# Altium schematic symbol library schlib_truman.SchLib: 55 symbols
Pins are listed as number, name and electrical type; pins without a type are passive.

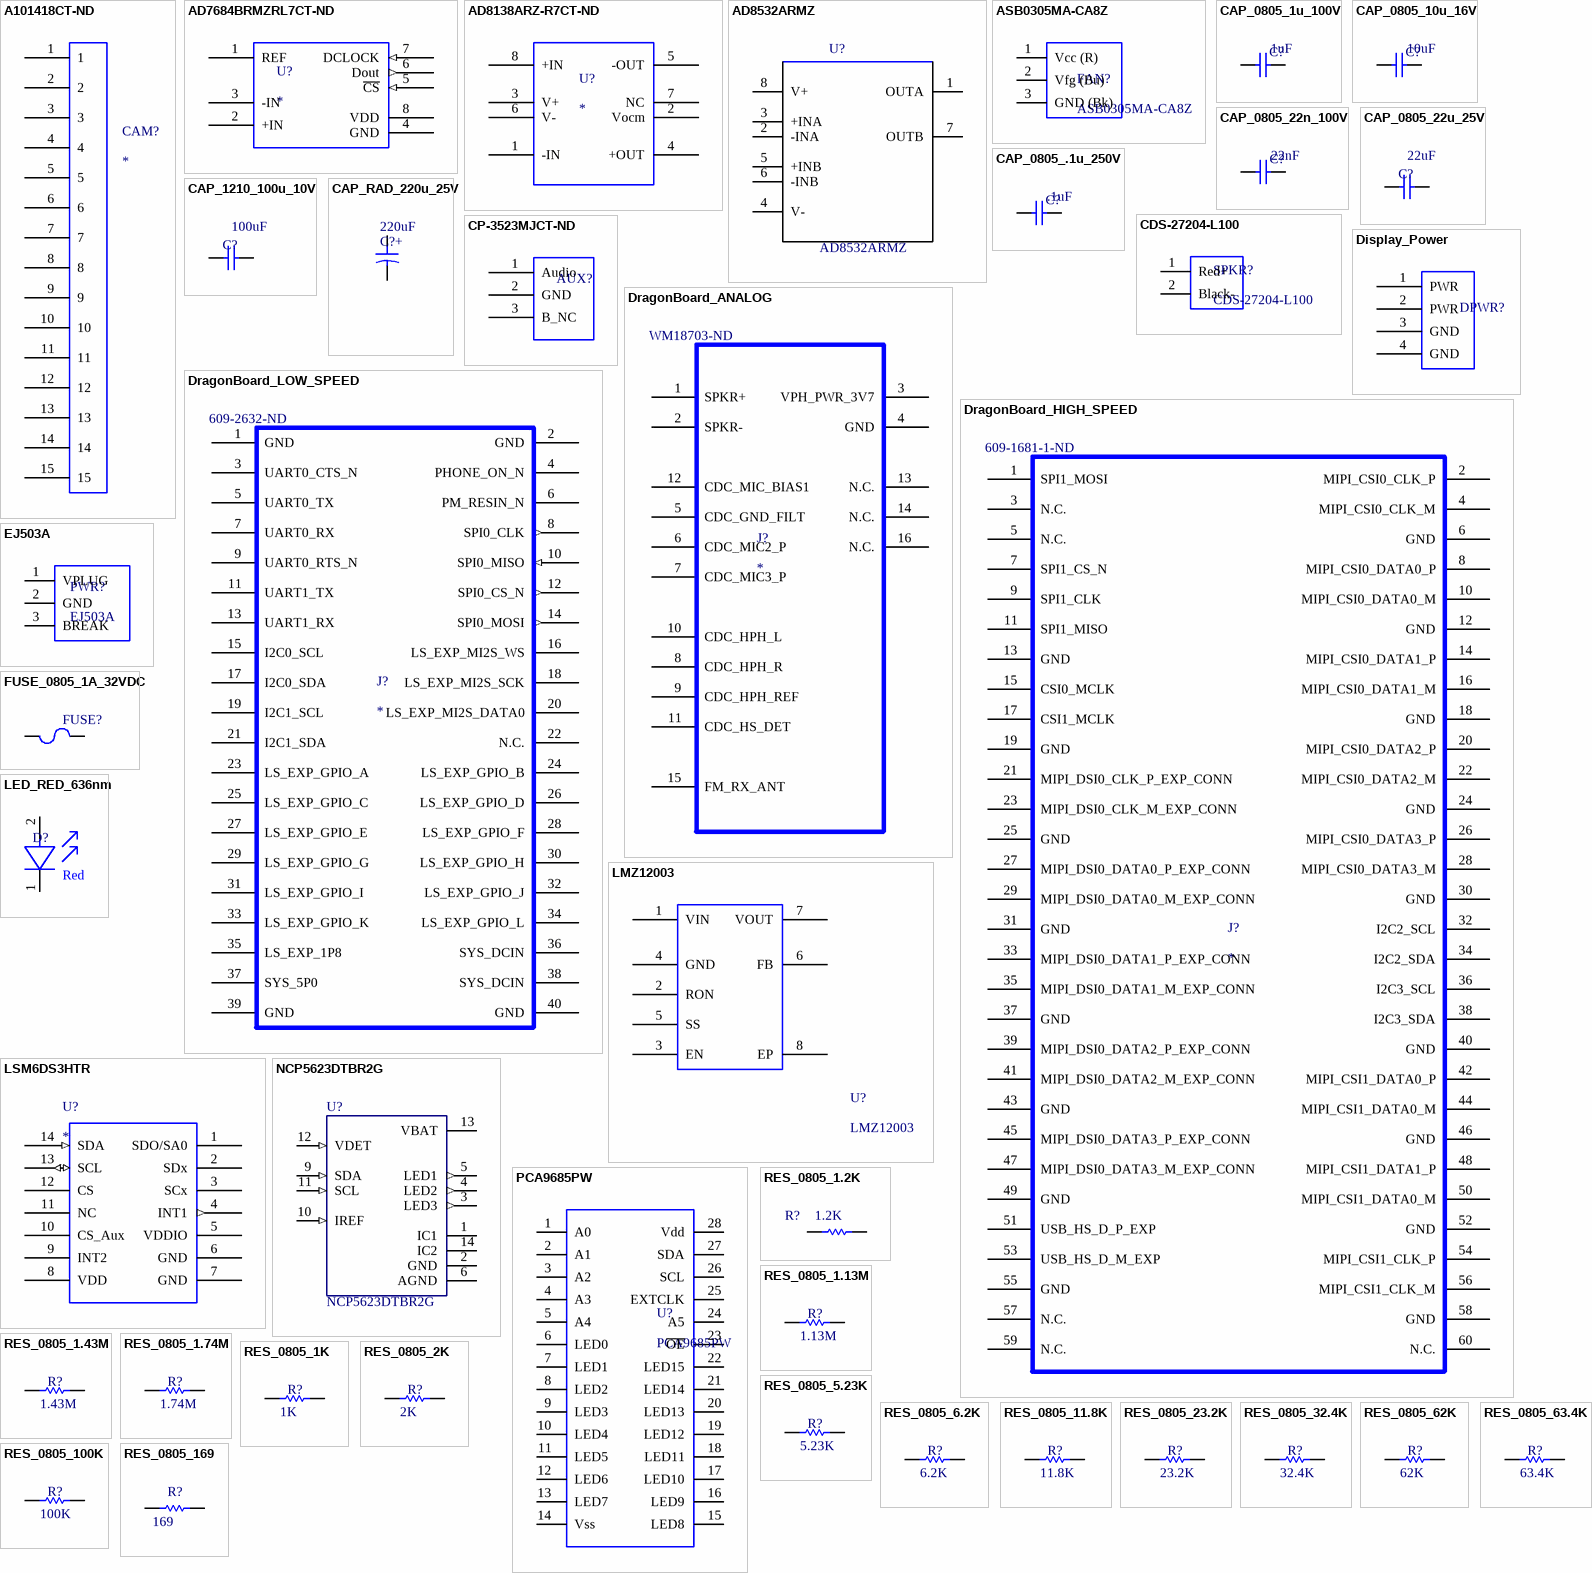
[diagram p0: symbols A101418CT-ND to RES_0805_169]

## A101418CT-ND
designator CAM?
CONN FPC VERT 15POS 1.00MM SMD; Manufacturer: TE Connectivity; Manufacturer Part Number: 1-1734248-5; Current Rating: 1A; Voltage Rating: 125V; Gender: Receptacle; Number of Positions: 15; Shielding: Unshielded; Connector Type: Connector,Receptacle,Socket; Wire/Cable Type: Flat Flex; Connector System: Flex-to-Board; Mating Alignment: Yes (With); PCB Mount Alignment: No (Without); PCB Mount Retention: With; PCB Mounting Orientation: Vertical; Pitch: 0.039inch
footprint ZIF_15pin
pins: 1, 2, 3, 4, 5, 6, 7, 8, 9, 10, 11, 12, 13, 14, 15

## AD7684BRMZRL7CT-ND
designator U?
IC ADC 16BIT 100KSPS DIFF 8MSOP; Manufacturer: Analog Devices; Manufacturer Part Number: AD7684BRMZRL7; Max Power Dissipation: 6mW; Supply Voltage: 5V; Min Supply Voltage: 2.7V; Max Supply Voltage: 5.5V; Number of Channels: 1; Interface: SPI; Power Consumption: 4mW; Resolution: 16b; Sampling Rate: 100KS/s; Signal to Noise Ratio (SNR): 91dB; Number of Bits: 16; Polarity: Bipolar; Supply Type: Single; Integral Nonlinearity (INL): 3LSB; Input Capacitance: 30pF; Full Scale Error: 15LSB; Min Input Voltage: 500mV
footprint MSOP8
pins: 1 REF, 2 +IN, 3 -IN, 4 GND, 5 ~{CS} (in), 6 Dout (out), 7 DCLOCK (in), 8 VDD

## AD8138ARZ-R7CT-ND
designator U?
SP Amp Differential ADC Driver Single ±5.5V/11V 8-Pin SOIC N T/R; Manufacturer: Analog Devices; Manufacturer Part Number: AD8138ARZ-R7; Min Supply Voltage: 2.7V; Max Supply Voltage: 11V; Min Dual Supply Voltage: 1.4V; Max Dual Supply Voltage: 5.5V; Common Mode Rejection Ratio: 70dB; Number of Channels: 1; Bandwidth: 320MHz; Slew Rate: 1150V/µs; Nominal Supply Current: 20mA; Max Power Dissipation: 550mW; Input Offset Voltage (Vos): 1mV; Input Bias Current: 7uA; Voltage Gain: 0.028dB; Input Resistance: 6MR
footprint SOIC127P600X175-8N (SOIC, 8-Leads, Body 4.90x3.90mm, Pitch 1.27mm, IPC Medium Density)
pins: 1 -IN, 2 Vocm, 3 V+, 4 +OUT, 5 -OUT, 6 V-, 7 NC, 8 +IN

## AD8532ARMZ
designator U?
OP Amp Dual General Purpose Rail to Rail I/O 6 Volt 8-Pin SOIC N; MF: Analog Devices; MP: AD8532ARZ; Min Supply Voltage: 2.7V; Max Supply Voltage: 6V; Voltage Gain: 98.06dB; Common Mode Rejection Ratio: 47dB; Unity Gain Bandwidth Product: 3MHz; Slew Rate: 5V/µs; Number of Circuits: 2; Input Bias Current: 50pA; Input Offset Voltage (Vos): 25mV; Operating Supply Current: 2.5mA; Output Current per Channel: 250mA; Input Voltage Noise Density: 45nV/sqrt Hz; Power Supply Rejection Ratio (PSRR): 55dB; Quiescent Current: 1.25mA; Settling Time: 1.4us; Supply Voltage: 5V
footprint SOIC127P600X175-8N (SOIC, 8-Leads, Body 4.90x3.90mm, Pitch 1.27mm, IPC Medium Density)
pins: 1 OUTA, 2 -INA, 3 +INA, 4 V- (power), 5 +INB, 6 -INB, 7 OUTB, 8 V+ (power)

## ASB0305MA-CA8Z
designator FAN?
FAN AXIAL 30X10MM 5VDC WIRE; Manufacturer: Delta Design; Airflow: 3.4CFM; Noise: 23dBA; Current Rating: 110mA; Max Power Dissipation: 550mW; RPM: 9000RPM; Bearing Type: Sleeve
footprint FAN_HEADER
pins: 1 Vcc (R), 2 Vfg (Bu), 3 GND (Bk)

## CAP_0805_1u_100V
designator C?  value 1uF  (hidden comment: CAP_0805_1u_100V)
CAP CER 1UF 100V X7S 0805; Manufacturer: TDK; Manufacturer Part Number: C2012X7S2A105K125AE; Tolerance: 10%
footprint CAPC2012X135N
pins: 1, 2

## CAP_0805_10u_16V
designator C?  value 10uF  (hidden comment: CAP_0805_10u_16V)
Cap Ceramic 10uF 16V X5R 10% SMD 0805 85C T/R; Manufacturer: Johanson Dielectrics; Manufacturer Part Number: 160R15X106KV4E
footprint CAPC2012X135N
pins: 1, 2

## CAP_0805_22n_100V
designator C?, comment value 22nF  (hidden comment: CAP_0805_m22n)
CAP CER 0.022UF 100V X7R 0805; Manufacturer: TDK; Manufacturer Part Number: CGJ4J2X7R2A223K125AA; Tolerance: 10%
footprint CAPC2012X135N
pins: 1, 2

## CAP_0805_22u_25V
designator C?  value 22uF  (hidden comment: CAP_0805_22u_25V)
22µF ±20% 25V X5R Ceramic Capacitor -55°C ~ 85°C Surface Mount, MLCC 0805 (2012 Metric) 0.079" L x 0.049" W (2.00mm x 1.25mm); Manufacturer: Samsung; Manufacturer Part Number: CL21A226MAQNNNE
footprint CAPC2012X135N
pins: 1, 2

## CAP_0805_.1u_250V
designator C?  value .1uF  (hidden comment: CAP_0805_.1u_250V)
Cap Ceramic 0.1uF 250V X7T 10% SMD 0805 125C Plastic T/R; Manufacturer: TDK; Manufacturer Part Number: C2012X7T2E104K125AE; Capacitance: 100nF
footprint CAPC2012X135N
pins: 1, 2

## CAP_1210_100u_10V
designator C?  value 100uF  (hidden comment: CAP_1210_100u_10V)
Cap Ceramic 100uF 10V X5R 20% SMD 1210 85C Embossed T/R; Manufacturer: Murata; Manufacturer Part Number: GRM32ER61A107ME20L; Dissipation Factor: 0.035%
footprint FP_1210
pins: 1, 2

## CAP_RAD_220u_25V
designator C?, comment Capacitance: 220uF  (hidden comment: CAP ALUM 220UF 20% 25V SMD)
Manufacturer: Nichicon; Manufacturer Part Number: UWT1E221MNL1GS; Dielectric Material: Aluminium; Ripple Current: 155mA; Leakage Current: 3uA; Life (Hours): 1000Hour; Dissipation Factor: 0.16%
footprint CAP_RADIAL (Aluminum Electrolytic Capacitor, Body 8.30x8.30x10.50mm, IPC Low Density)
pins: 1, 2

## CDS-27204-L100
designator SPKR?
4 Ohm Magnetic Speaker 2W 20Hz ~ 20kHz Top Rectangular 93dB; Manufacturer: CUI; Impedance: 4R; Max Power Dissipation: 2.5W
footprint Speaker_Header
pins: 1 Red+, 2 Black-

## CP-3523MJCT-ND
designator AUX?  (value not drawn)
3.50mm (0.141", 1/8", Mini Plug) - Headphone Phone Jack Mono Connector Solder; Manufacturer: CUI; Manufacturer Part Number: MJ-3523-SMT-TR; Gender: Female; Shielding: Unshielded; Current Rating: 1A
footprint Audio_Conn_Mono
pins: 1 Audio, 2 GND, 3 B_NC

## Display_Power
designator DPWR?  (value not drawn)
4 Position Thru Hole Connection; Manufacturer: N/A - Just Thru Hole Vias
footprint LCD_POWER_HEADER
pins: 1 PWR, 2 PWR, 3 GND, 4 GND

## DragonBoard_ANALOG
designator J?  Supplier Part Number 1: WM18703-ND
Conn Socket Strip RCP 16 POS 2mm Solder ST SMD Tube; Manufacturer: Molex; Manufacturer Part Number: 0791091007; Connector Type: Receptacle,Socket; Number of Positions: 16; Gender: Female; Max Voltage Rating (AC): 125V; Contact Resistance: 25mR; Row Spacing: 0.079inch
footprint 16_PIN_ANALOG_CONN
pins: 1 SPKR+, 2 SPKR-, 3 VPH_PWR_3V7, 4 GND, 5 CDC_GND_FILT, 6 CDC_MIC2_P, 7 CDC_MIC3_P, 8 CDC_HPH_R, 9 CDC_HPH_REF, 10 CDC_HPH_L, 11 CDC_HS_DET, 12 CDC_MIC_BIAS1, 13 N.C., 14 N.C., 15 FM_RX_ANT, 16 N.C.

## DragonBoard_HIGH_SPEED
designator J?  Supplier Part Number 1: 609-1681-1-ND
60 Position Connector Plug, Center Strip Contacts Surface Mount Gold; Manufacturer: Amphenol FCI; Manufacturer Part Number: 61083-064402LF; Contact Resistance: 50mR; Number of Positions: 60; Max Voltage Rating (AC): 100V; Current Rating: 500mA; Gender: Male; Pitch: 0.8mm; Stack Height: 7.7mm
footprint DB_HIGH_SPEED
pins: 1 SPI1_MOSI, 2 MIPI_CSI0_CLK_P, 3 N.C., 4 MIPI_CSI0_CLK_M, 5 N.C., 6 GND, 7 SPI1_CS_N, 8 MIPI_CSI0_DATA0_P, 9 SPI1_CLK, 10 MIPI_CSI0_DATA0_M, 11 SPI1_MISO, 12 GND, 13 GND, 14 MIPI_CSI0_DATA1_P, 15 CSI0_MCLK, 16 MIPI_CSI0_DATA1_M, 17 CSI1_MCLK, 18 GND, 19 GND, 20 MIPI_CSI0_DATA2_P, 21 MIPI_DSI0_CLK_P_EXP_CONN, 22 MIPI_CSI0_DATA2_M, 23 MIPI_DSI0_CLK_M_EXP_CONN, 24 GND, 25 GND, 26 MIPI_CSI0_DATA3_P, 27 MIPI_DSI0_DATA0_P_EXP_CONN, 28 MIPI_CSI0_DATA3_M, 29 MIPI_DSI0_DATA0_M_EXP_CONN, 30 GND, 31 GND, 32 I2C2_SCL, 33 MIPI_DSI0_DATA1_P_EXP_CONN, 34 I2C2_SDA, 35 MIPI_DSI0_DATA1_M_EXP_CONN, 36 I2C3_SCL, 37 GND, 38 I2C3_SDA, 39 MIPI_DSI0_DATA2_P_EXP_CONN, 40 GND, 41 MIPI_DSI0_DATA2_M_EXP_CONN, 42 MIPI_CSI1_DATA0_P, 43 GND, 44 MIPI_CSI1_DATA0_M, 45 MIPI_DSI0_DATA3_P_EXP_CONN, 46 GND, 47 MIPI_DSI0_DATA3_M_EXP_CONN, 48 MIPI_CSI1_DATA1_P, 49 GND, 50 MIPI_CSI1_DATA0_M, 51 USB_HS_D_P_EXP, 52 GND, 53 USB_HS_D_M_EXP, 54 MIPI_CSI1_CLK_P, 55 GND, 56 MIPI_CSI1_CLK_M, 57 N.C., 58 GND, 59 N.C., 60 N.C.

## DragonBoard_LOW_SPEED
designator J?  Supplier Part Number 1: 609-2632-ND
40 Positions Header, Unshrouded Connector 0.079" (2.00mm) Surface Mount Gold, GXT™; Manufacturer: Amphenol FCI; Manufacturer Part Number: 57202-G52-20LF; Number of Positions: 40; Insulation Resistance: 1GR; Max Voltage Rating (AC): 650V; Gender: Male; Connector Type: Male Pin; Contact Resistance: 25mR; Current Rating: 2A; Pitch: 2mm; Row Spacing: 0.079inch; Mating Post Length: 4mm
footprint 57202_40_PIN_HEADER
pins: 1 GND, 2 GND, 3 UART0_CTS_N, 4 PHONE_ON_N, 5 UART0_TX, 6 PM_RESIN_N, 7 UART0_RX, 8 SPI0_CLK (out), 9 UART0_RTS_N, 10 SPI0_MISO (in), 11 UART1_TX, 12 SPI0_CS_N (out), 13 UART1_RX, 14 SPI0_MOSI (out), 15 I2C0_SCL, 16 LS_EXP_MI2S_WS, 17 I2C0_SDA, 18 LS_EXP_MI2S_SCK, 19 I2C1_SCL, 20 LS_EXP_MI2S_DATA0, 21 I2C1_SDA, 22 N.C., 23 LS_EXP_GPIO_A, 24 LS_EXP_GPIO_B, 25 LS_EXP_GPIO_C, 26 LS_EXP_GPIO_D, 27 LS_EXP_GPIO_E, 28 LS_EXP_GPIO_F, 29 LS_EXP_GPIO_G, 30 LS_EXP_GPIO_H, 31 LS_EXP_GPIO_I, 32 LS_EXP_GPIO_J, 33 LS_EXP_GPIO_K, 34 LS_EXP_GPIO_L, 35 LS_EXP_1P8, 36 SYS_DCIN, 37 SYS_5P0, 38 SYS_DCIN, 39 GND, 40 GND

## EJ503A
designator PWR?
DC Barrel Jack 2.1mm x 5.5mm 12V 5A; Manufacturer: Memory Protection Devices
footprint BARRELJACK
pins: 1 VPLUG, 2 GND, 3 BREAK

## FUSE_0805_1A_32VDC
designator FUSE?  (value not drawn)
FUSE 1.00A 0805 VFAST SMD; Manufacturer: Vishay; Manufacturer Part Number: MFU0805FF01000P100; Voltage Rating (DC): 32V; Current Rating: 1A; DC Cold Resistance: 185mR; Approvals: UL
footprint RES0805
pins: 1, 2

## LED_RED_636nm
designator D?  Color: Red  (hidden comment: LED_RED_636nm)
Standard LEDs - SMD Surface Mount LEDs; Manufacturer: Lumex; Manufacturer Part Number: SML-LXR85SIC-TR; Lens Colour: Colorless; Viewing Angle: 160°; Forward Current: 20mA; Forward Voltage: 2V; Power Rating: 80mW; Luminous Intensity: 70mcd; Lens Transparency: Clear; Wavelength: 636nm
footprint POWERLED_FP
pins: 1 Cathode, 2 Anode

## LMZ12003
designator U?
POWER MODULE, TO-PMOD-7, FULL REEL; Manufacturer: Texas Instruments; Manufacturer Part Number: LMZ12003TZ-ADJ/NOPB; Min Input Voltage: 4.5V; Max Input Voltage: 20V; Number of Outputs: 1; Output Current: 3A; Output Voltage: 6V; Switching Frequency: 1MHz; Efficiency: 92%; Min Output Voltage: 800mV; Quiescent Current: 1mA; Max Power Dissipation: 18W
footprint TO-PMOD-7
pins: 1 VIN, 2 RON, 3 EN, 4 GND, 5 SS, 6 FB, 7 VOUT, 8 EP

## LSM6DS3HTR
designator U?
Accelerometer and Gyroscope 14-Pin LGA T/R; Manufacturer: STMicroelectronics; Manufacturer Part Number: LSM6DS3HTR
footprint PQFN50P300X250X86_HS-15N (PQFN, 14-Leads, Body 3.00x2.50mm, Pitch 0.50mm, Thermal Pad 1.45x1.95mm, IPC Medium Density)
pins: 1 SDO/SA0, 2 SDx, 3 SCx, 4 INT1 (out), 5 VDDIO (power), 6 GND (power), 7 GND (power), 8 VDD (power), 9 INT2, 10 CS_Aux, 11 NC, 12 CS, 13 SCL (io), 14 SDA (in)

## NCP5623DTBR2G
designator U?
LED DRVR 3Segment 3.3V/5V 14-Pin TSSOP T/R; MF: ON Semiconductor; Nominal Supply Current: 1mA; Min Supply Voltage: 2.7V; Max Supply Voltage: 5.5V; Number of Outputs: 3; Frequency: 1.2MHz; Max Power Dissipation: 200mW; Output Voltage: 5.7V; Max Supply Current: 350uA; Power Dissipation: 235mW; Output Current: 90mA; Switching Frequency: 1MHz
footprint SOP65P640X120-14N
pins: 1 IC1, 2 GND, 3 LED3 (out), 4 LED2 (out), 5 LED1 (out), 6 AGND, 9 SDA (in), 10 IREF (in), 11 SCL (in), 12 VDET (in), 13 VBAT (power), 14 IC2

## PCA9685PW
designator U?
IC LED DRIVER RGBA 28-TSSOP; Manufacturer: NXP Semiconductors; Manufacturer Part Number: PCA9685PW,118; Number of Outputs: 16; Frequency: 1MHz; Max Supply Voltage: 5.5V; Min Supply Voltage: 2.3V; Nominal Supply Current: 10A; Output Current per Channel: 25mA; High Level Output Current: 10mA; Low Level Output Current: 400A; Power Dissipation: 400W
footprint TSSOP28
pins: 1 A0, 2 A1, 3 A2, 4 A3, 5 A4, 6 LED0, 7 LED1, 8 LED2, 9 LED3, 10 LED4, 11 LED5, 12 LED6, 13 LED7, 14 Vss, 15 LED8, 16 LED9, 17 LED10, 18 LED11, 19 LED12, 20 LED13, 21 LED14, 22 LED15, 23 ~{OE}, 24 A5, 25 EXTCLK, 26 SCL, 27 SDA, 28 Vdd

## RES_0805_1.2K
designator R?  Resistance: 1.2K  (hidden comment: *)
Res Thick Film 0805 1.2K Ohm 5% 0.125W(1/8W) ±200ppm/C Molded SMD Automotive T/R; Manufacturer: Stackpole Electronics; Manufacturer Part Number: RMCF0805JT1K20; Max Power Dissipation: 125mW; Temperature Coefficient: 200ppm/°C
footprint RES0805
pins: 1, 2

## RES_0805_1.13M
designator R?, comment RES_1.13M  (value not drawn)
Res Thick Film 0805 1.13M Ohm 1% 1/8W 100ppm/C Molded SMD Punched Carrier T/R; Manufacturer: Panasonic; Manufacturer Part Number: ERJ-6ENF1134V; Resistance: 1.13MR; Power Rating: 125mW; Voltage Rating: 150V; Temperature Coefficient: 100ppm/°C
footprint RES0805
pins: 1, 2

## RES_0805_1.43M
designator R?, comment RES_1.43M  (value not drawn)
RES SMD 1.43M OHM 1% 1/8W 0805; Manufacturer: Yageo; Manufacturer Part Number: RC0805FR-071M43L; Voltage Rating: 150V; Resistance: 1.43MR; Power Rating: 125mW; Temperature Coefficient: 100ppm/°C
footprint RES0805
pins: 1, 2

## RES_0805_1.74M
designator R?  (value not drawn)
RES SMD 1.74M OHM 1% 1/8W 0805; Manufacturer: Yageo; Manufacturer Part Number: RC0805FR-071M74L; Resistance: 1.74MR; Power Rating: 125mW; Voltage Rating: 150V; Temperature Coefficient: 100ppm/°C
footprint RES0805
pins: 1, 2

## RES_0805_1K
designator R?  (value not drawn)
RES SMD 1K OHM 1% 1/8W 0805; Manufacturer: Yageo; Manufacturer Part Number: RC0805FR-071KL; Resistance: 1KR; Temperature Coefficient: 100ppm/°C; Voltage Rating (DC): 150V; Power Rating: 125mW
footprint RES0805
pins: 1, 2

## RES_0805_2K
designator R?  (value not drawn)
RES SMD 2K OHM 5% 1/8W 0805; Manufacturer: Yageo; Manufacturer Part Number: RC0805JR-072KL; Resistance: 2KR; Power Rating: 125mW; Voltage Rating: 150V; Temperature Coefficient: 100ppm/°C
footprint RES0805
pins: 1, 2

## RES_0805_5.23K
designator R?, comment RES_5.23K  (value not drawn)
Thick Film Resistors 5.23K OHM 1%; Manufacturer: Yageo; Manufacturer Part Number: RC0805FR-075K23L; Resistance: 5.23KR; Power Rating: 125mW; Voltage Rating: 150V; Temperature Coefficient: 100ppm/°C
footprint RES0805
pins: 1, 2

## RES_0805_6.2K
designator R?, comment RES_6.2K  (value not drawn)
Yageo RC0805 Series Thick Film Surface Mount Resistor 0805 Case 6.2k 1% 0.125W 100ppm/C; Manufacturer Part Number: RC0805FR-076K2L; Power Rating: 125mW; Resistance: 6.2KR; Temperature Coefficient: 100ppm/°C; Voltage Rating (DC): 150V
footprint RES0805
pins: 1, 2

## RES_0805_11.8K
designator R?  (value not drawn)
RES SMD 11.8K OHM 1% 1/8W 0805; Manufacturer: Yageo; Manufacturer Part Number: RC0805FR-0711K8L; Resistance: 11.8KR; Temperature Coefficient: 100ppm/°C; Voltage Rating (DC): 150V; Power Rating: 125mW
footprint RES0805
pins: 1, 2

## RES_0805_23.2K
designator R?  (value not drawn)
RESISTOR, THICK FILM, 23.2KOHM, 125mW, ± 1%; Manufacturer: Panasonic ECG; Manufacturer Part Number: ERJ-6ENF2322V; Resistance: 23.2KR; Voltage Rating: 150V; Temperature Coefficient: 100ppm/°C
footprint RES0805
pins: 1, 2

## RES_0805_32.4K
designator R?  (value not drawn)
Res Thick Film 0805 32.4K Ohm 1% 0.125W(1/8W) ±100ppm/C Molded SMD Automotive Punched T/R; Manufacturer: Panasonic ECG; Manufacturer Part Number: ERJ-6ENF3242V; Voltage Rating: 150V; Resistance: 32.4KR; Power Rating: 125mW; Temperature Coefficient: 100ppm/°C
footprint RES0805
pins: 1, 2

## RES_0805_62K
designator R?  (value not drawn)
RES SMD 62K OHM 1% 1/8W 0805; Manufacturer: Yageo; Manufacturer Part Number: RC0805FR-0762KL; Resistance: 62KR; Power Rating: 125mW; Temperature Coefficient: 100ppm/°C; Voltage Rating (DC): 150V
footprint RES0805
pins: 1, 2

## RES_0805_63.4K
designator R?, comment RES_63.4K  (value not drawn)
RES SMD 63.4K OHM 1% 1/8W 0805; Manufacturer: Yageo; Manufacturer Part Number: RC0805FR-0763K4L; Resistance: 63.4KR; Power Rating: 125mW; Voltage Rating: 150V; Temperature Coefficient: 100ppm/°C
footprint RES0805
pins: 1, 2

## RES_0805_100K
designator R?  (value not drawn)
Res Thick Film 0805 100K Ohm 1% 0.125W(1/8W) ±100ppm/C Molded SMD Automotive Punched T/R; Manufacturer: Panasonic ECG; Manufacturer Part Number: ERJ-6ENF1003V; Resistance: 100KR; Power Rating: 125mW; Temperature Coefficient: 100ppm/°C; Voltage Rating (DC): 150V
footprint RES0805
pins: 1, 2

## RES_0805_169
designator R?, comment 169 Ohm  (value not drawn)
RES SMD 169 OHM 1% 1/8W 0805; Manufacturer: Yageo; Manufacturer Part Number: RC0805FR-07169RL; Resistance: 169R; Temperature Coefficient: 100ppm/°C; Power Rating: 125mW; Voltage Rating: 150V
footprint RES0805
pins: 1, 2

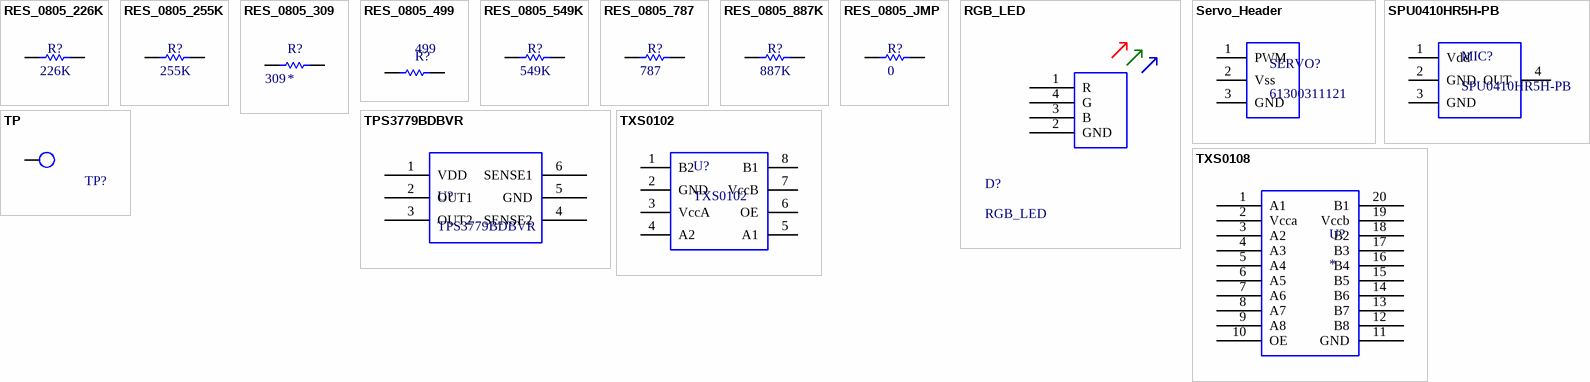
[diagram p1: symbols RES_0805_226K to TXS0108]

## RES_0805_226K
designator R?  (value not drawn)
Res Thick Film 0805 226K Ohm 1% 1/8W ±100ppm/C Molded SMD Punched Carrier T/R; Manufacturer: Panasonic ECG; Manufacturer Part Number: ERJ-6ENF2263V; Resistance: 226KR; Power Rating: 125mW; Voltage Rating: 150V; Temperature Coefficient: 100ppm/°C
footprint RES0805
pins: 1, 2

## RES_0805_255K
designator R?  (value not drawn)
RES SMD 255K OHM 1% 1/8W 0805; Manufacturer: Yageo; Manufacturer Part Number: RC0805FR-07255KL; Power Rating: 125mW; Resistance: 255KR; Voltage Rating: 150V; Temperature Coefficient: 100ppm/°C
footprint RES0805
pins: 1, 2

## RES_0805_309
designator R?
RES SMD 309 OHM 1% 1/8W 0805; Manufacturer: Yageo; Manufacturer Part Number: RC0805FR-07309RL; Resistance: 309R; Temperature Coefficient: 100ppm/°C; Power Rating: 125mW; Voltage Rating: 150V
footprint RES0805
pins: 1, 2

## RES_0805_499
designator R?  Resistance: 499  (hidden comment: *)
Res Thick Film 0805 499 Ohm 1% 0.125W(1/8W) ±100ppm/C Molded SMD Automotive T/R; Manufacturer: Stackpole Electronics; Manufacturer Part Number: RMCF0805FT499R; Power Rating: 125mW; Temperature Coefficient: 100ppm/°C
footprint RES0805
pins: 1, 2

## RES_0805_549K
designator R?, comment RES_549K  (value not drawn)
RES SMD 549K OHM 1% 1/8W 0805; Manufacturer: Vishay; Manufacturer Part Number: CRCW0805549KFKEA; Resistance: 549KR; Power Rating: 125mW; Voltage Rating: 150V; Temperature Coefficient: 100ppm/°C
footprint RES0805
pins: 1, 2

## RES_0805_787
designator R?, comment RES_787  (value not drawn)
RES SMD 787 OHM 1% 1/8W 0805; Manufacturer: Yageo; Manufacturer Part Number: RC0805FR-07787RL; Resistance: 787R; Max Power Dissipation: 125mW; Temperature Coefficient: 100ppm/°C; Voltage Rating (DC): 150V
footprint RES0805
pins: 1, 2

## RES_0805_887K
designator R?, comment RES_887K  (value not drawn)
Thick Film Resistors - SMD 887K OHM 1%; Manufacturer: Yageo; Manufacturer Part Number: RC0805FR-07887KL; Voltage Rating (DC): 150V; Power Rating: 125mW; Resistance: 887KR; Temperature Coefficient: 100ppm/°C
footprint RES0805
pins: 1, 2

## RES_0805_JMP
designator R?  (value not drawn)
RES, THICK FILM, 0R, 0.125W, 0805; Manufacturer: Yageo; Manufacturer Part Number: RC0805JR-070RL; Resistance: 0mR; Tolerance: 5%; Voltage Rating: 150V; Power Rating: 125mW; Temperature Coefficient: 200ppm/°C
footprint RES0805
pins: 1, 2

## RGB_LED
designator D?
WP154A4SUREQBFZGC; Manufacturer: Kingbright; Colour: Blue,Green,Red; Luminous Intensity: 900mcd; Lens Style: Dome,Clear; Forward Current: 20mA; Forward Voltage: 3.3V; Viewing Angle: 50°; Dominant Wavelength: 465nm
footprint RGB_LED
pins: 1 R, 2 GND (power), 3 B, 4 G

## Servo_Header
designator SERVO?, comment 61300311121
Board-To-Board Connector, Vertical, WR-PHD Series, Through Hole, Header, 3 Contacts, 2.54 mm; Manufacturer: Wurth Electronics; Number of Positions: 3; Gender: Male; Connector Type: Male Pin; Pitch: 0.1inch
footprint SERVO_HEADER
pins: 1 PWM, 2 Vss, 3 GND

## SPU0410HR5H-PB
designator MIC?
MIC MEMS ANALOG OMNI -42DB; Manufacturer: Knowles; Shape: Rectangular; Impedance: 300R; Voltage Rating: 3.6V; Direction: Omnidirectional; Operating Supply Current: 250uA; Signal to Noise Ratio (SNR): 59dB
footprint MIC_FP
pins: 1 Vdd, 2 GND, 3 GND, 4 OUT

## TP
designator TP?  (value not drawn)
Testpoint_1206; Manufacturer: TE Connectivity; Manufacturer Part Number: 1625854-4; Resistance: 0mR
footprint TestPoint_1206
pins: 1

## TPS3779BDBVR
designator U?
Voltage Detector, Active-Low, Push-Pull Reset, 2-Monitors, 1.5V-6.5Vin, SOT-23-6; Manufacturer: Texas Instruments; Manufacturer Part Number: TPS3779BDBVT; Number of Voltages Monitored: 2; Reset: Active Low; Threshold Voltage: 1.194V; Min Supply Voltage: 1.5V; Max Supply Voltage: 6.5V; Quiescent Current: 2uA
footprint DBV (R-PDSO-G6) (6 pin dbv)
pins: 1 VDD, 2 OUT1, 3 OUT2, 4 SENSE2, 5 GND, 6 SENSE1

## TXS0102
designator U?
IC VOLT-LVL TRANSL 2BIT BI SM8; Manufacturer: Texas Instruments; Manufacturer Part Number: TXS0102DCTR; Min Supply Voltage: 1.65V; Max Supply Voltage: 5.5V; Propagation Delay: 260ns; Number of Inputs: 2; Data Rate: 24Mbps; Logic Function: Translator; Low Level Output Current: 1mA; High Level Output Current: -20uA; Quiescent Current: 14.4uA; Turn-On Delay Time: 102ns
footprint DCT8_LEVELSHIFT
pins: 1 B2, 2 GND, 3 VccA, 4 A2, 5 A1, 6 OE, 7 VccB, 8 B1

## TXS0108
designator U?
TRANSLATOR, VOLTAGE, 8BIT, 20TSSOP; Manufacturer: Texas Instruments; Manufacturer Part Number: TXS0108EPWR; Output Current: 620µA; Propagation Delay: 4.8ns; Logic Case Style: TSSOP; No. of Pins: 20; Supply Voltage Min: 1.2V; Logic Type: Voltage Level Translator; Supply Voltage Max: 5.5V; No. of Inputs: 8; SVHC: No SVHC (16-Jun-2014)
footprint TSSOP20
pins: 1 A1, 2 Vcca, 3 A2, 4 A3, 5 A4, 6 A5, 7 A6, 8 A7, 9 A8, 10 OE, 11 GND, 12 B8, 13 B7, 14 B6, 15 B5, 16 B4, 17 B3, 18 B2, 19 Vccb, 20 B1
